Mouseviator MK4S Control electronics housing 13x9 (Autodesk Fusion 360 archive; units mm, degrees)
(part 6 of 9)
sketch "Sketch1" plane through (0, 0, 5) normal (0, 0, 1) x axis (-1, 0, 0)
  line L1 (-98.9644, -53.9879) -> (-98.9644, -59.9879)
  line L2 (-92.9644, -53.9879) -> (-98.9644, -53.9879)
  line L3 (-92.9644, -59.9879) -> (-92.9644, -53.9879)
  line L4 (-98.9644, -59.9879) -> (-92.9644, -59.9879)
  line L5 (-12.9644, 60.0121) -> (-12.9644, 66.0121)
  line L6 (-18.9644, 60.0121) -> (-12.9644, 60.0121)
  line L7 (-18.9644, 66.0121) -> (-18.9644, 60.0121)
  line L8 (-12.9644, 66.0121) -> (-18.9644, 66.0121)
  line L9 (-45.9644, -51.9879) -> (-20.9644, -51.9879)
  line L10 (-40.9644, -54.9879) -> (-45.9644, -51.9879)
  line L11 (-70.9644, -54.9879) -> (-40.9644, -54.9879)
  line L12 (-65.9644, -51.9879) -> (-70.9644, -54.9879)
  line L13 (-90.9644, -51.9879) -> (-65.9644, -51.9879)
  line L14 (-90.9644, -6.9879) -> (-90.9644, -51.9879)
  line L15 (-93.9644, -11.9879) -> (-90.9644, -6.9879)
  line L16 (-93.9644, 18.0121) -> (-93.9644, -11.9879)
  line L17 (-90.9644, 13.0121) -> (-93.9644, 18.0121)
  line L18 (-90.9644, 58.0121) -> (-90.9644, 13.0121)
  line L19 (-65.9644, 58.0121) -> (-90.9644, 58.0121)
  line L20 (-70.9644, 61.0121) -> (-65.9644, 58.0121)
  line L21 (-40.9644, 61.0121) -> (-70.9644, 61.0121)
  line L22 (-45.9644, 58.0121) -> (-40.9644, 61.0121)
  line L23 (-20.9644, 58.0121) -> (-45.9644, 58.0121)
  line L24 (-20.9644, 13.0121) -> (-20.9644, 58.0121)
  line L25 (-17.9644, 18.0121) -> (-20.9644, 13.0121)
  line L26 (-17.9644, -11.9879) -> (-17.9644, 18.0121)
  line L27 (-20.9644, -6.9879) -> (-17.9644, -11.9879)
  line L28 (-20.9644, -51.9879) -> (-20.9644, -6.9879)
  line L29 (-12.9644, -53.9879) -> (-18.9644, -53.9879)
  line L30 (-12.9644, -59.9879) -> (-12.9644, -53.9879)
  line L31 (-18.9644, -59.9879) -> (-12.9644, -59.9879)
  line L32 (-18.9644, -53.9879) -> (-18.9644, -59.9879)
  line L33 (-98.9644, 60.0121) -> (-92.9644, 60.0121)
  line L34 (-98.9644, 66.0121) -> (-98.9644, 60.0121)
  line L35 (-92.9644, 66.0121) -> (-98.9644, 66.0121)
  line L36 (-92.9644, 60.0121) -> (-92.9644, 66.0121)
  line L37 (-10.9644, -6.9879) -> (-10.9644, -61.9879)
  line L38 (-13.9644, -11.9879) -> (-10.9644, -6.9879)
  line L39 (-13.9644, 18.0121) -> (-13.9644, -11.9879)
  line L40 (-10.9644, 13.0121) -> (-13.9644, 18.0121)
  line L41 (-10.9644, 68.0121) -> (-10.9644, 13.0121)
  line L42 (-45.9644, 68.0121) -> (-10.9644, 68.0121)
  line L43 (-40.9644, 65.0121) -> (-45.9644, 68.0121)
  line L44 (-70.9644, 65.0121) -> (-40.9644, 65.0121)
  line L45 (-65.9644, 68.0121) -> (-70.9644, 65.0121)
  line L46 (-100.9644, 68.0121) -> (-65.9644, 68.0121)
  line L47 (-100.9644, 13.0121) -> (-100.9644, 68.0121)
  line L48 (-97.9644, 18.0121) -> (-100.9644, 13.0121)
  line L49 (-97.9644, -11.9879) -> (-97.9644, 18.0121)
  line L50 (-100.9644, -6.9879) -> (-97.9644, -11.9879)
  line L51 (-100.9644, -61.9879) -> (-100.9644, -6.9879)
  line L52 (-65.9644, -61.9879) -> (-100.9644, -61.9879)
  line L53 (-70.9644, -58.9879) -> (-65.9644, -61.9879)
  line L54 (-40.9644, -58.9879) -> (-70.9644, -58.9879)
  line L55 (-45.9644, -61.9879) -> (-40.9644, -58.9879)
  line L56 (-10.9644, -61.9879) -> (-45.9644, -61.9879)
  line L57 (-100.9644, -61.9879) -> (-10.9644, -61.9879)
  line L58 (-99.9644, -60.9879) -> (-100.9644, -61.9879)
  line L59 (-91.9644, -60.9879) -> (-99.9644, -60.9879)
  line L60 (-91.9644, -59.9879) -> (-91.9644, -60.9879)
  line L61 (-19.9644, -59.9879) -> (-91.9644, -59.9879)
  line L62 (-19.9644, -60.9879) -> (-19.9644, -59.9879)
  line L63 (-11.9644, -60.9879) -> (-19.9644, -60.9879)
  line L64 (-10.9644, -61.9879) -> (-11.9644, -60.9879)
  line L65 (-99.9437, -61.0379) -> (-100.8937, -61.9879)
  line L66 (-91.9144, -61.0379) -> (-99.9437, -61.0379)
  line L67 (-91.9144, -60.0379) -> (-91.9144, -61.0379)
  line L68 (-20.0144, -60.0379) -> (-91.9144, -60.0379)
  line L69 (-20.0144, -61.0379) -> (-20.0144, -60.0379)
  line L70 (-11.9851, -61.0379) -> (-20.0144, -61.0379)
  line L71 (-11.0351, -61.9879) -> (-11.9851, -61.0379)
  circle C1 centre (-24.4644, 61.5121) radius 1.7
  circle C2 centre (-93.9644, 54.5121) radius 1.7
  circle C3 centre (-87.4644, -55.4879) radius 1.7
  circle C4 centre (-17.4644, -48.4879) radius 1.7
  circle C5 centre (-24.4644, -55.4879) radius 1.7
  circle C6 centre (-93.9644, -48.4879) radius 1.7
  circle C7 centre (-87.4644, 61.5121) radius 1.7
  circle C8 centre (-17.4644, 54.5121) radius 1.7
  point P46 (-10.9644, -61.9879)
  point P74 (-10.9644, -61.9879)
  point P61 (-100.9644, -61.9879)
  point P76 (-100.9644, -61.9879)
  point P68 (-99.9644, -60.9879)
  point P77 (-99.9644, -60.9879)
  point P69 (-91.9644, -60.9879)
  point P78 (-91.9644, -60.9879)
  point P70 (-91.9644, -59.9879)
  point P79 (-91.9644, -59.9879)
  point P71 (-19.9644, -59.9879)
  point P80 (-19.9644, -59.9879)
  point P72 (-19.9644, -60.9879)
  point P81 (-19.9644, -60.9879)
  point P73 (-11.9644, -60.9879)
  point P82 (-11.9644, -60.9879)
  point P89 (-11.0351, -61.9879)
  point P90 (-100.8937, -61.9879)
  point P75 (-100.9644, -61.9879)
  coincident P46 P74
  coincident P61 P76
  coincident P68 P77
  coincident P69 P78
  coincident P70 P79
  coincident P71 P80
  coincident P72 P81
  coincident P73 P82
  coincident L56 P89
  coincident L52 P90
  dimension "d228_1_1" distance L57 L70 = 0.95 (= "side_wall_thick1")
  dimension "d229_1_1" distance L57 L68 = 1.95 (= "side_wall_thick2")
  dimension "d230_1_1" distance L57 L66 = 0.95 (= "side_wall_thick1")
  dimension "d231_1_1" distance P74 P75 = 90 (= "plate_height")
  dimension "d232_1_1" distance L64 L71 = 0.05 (= "wall_clearance")
  dimension "d233_1_1" distance L58 L65 = 0.05 (= "wall_clearance")
  dimension "d234_1_1" angle L57 L58 = 45 (= "wall_rorner_angle")
  dimension "d235_1_1" distance P74 L69 = 9.05 (= "side_wall_col_length")
  dimension "d244_1_1" distance P75 L67 = 9.05 (= "side_wall_col_length")
extrude "Extrude1" new body sketch "Sketch1" profile of L52 L53 L55 L56 blind 69.9 (= "column_height - ( 2 * wall_clearance )") named "d217_1_1" from offset 0.05 (= "wall_clearance") named "d216_1_1"
sketch "Sketch2" plane through (0, 61.9879, 0) normal (0, 1, 0) x axis (-1, 0, 0)
  line L1 (-11.0351, 74.95) -> (-100.8937, 74.95)
  line L2 (-100.8937, 74.95) -> (-100.8937, 5.05)
  line L3 (-11.0351, 74.95) -> (-11.0351, 5.05)
  line L4 (-11.0351, 5.05) -> (-100.8937, 5.05)
  line L5 (-11.0351, 74.95) -> (-11.0351, 5.05)
  line L6 (-100.8937, 74.95) -> (-11.0351, 74.95)
  line L7 (-100.8937, 5.05) -> (-100.8937, 74.95)
  line L8 (-90.8937, 64.95) -> (-21.0351, 64.95)
  line L9 (-90.8937, 15.05) -> (-90.8937, 64.95)
  line L10 (-21.0351, 15.05) -> (-90.8937, 15.05)
  line L11 (-21.0351, 64.95) -> (-21.0351, 15.05)
  circle C1 centre (-95.9644, 60) radius 1.7
  circle C2 centre (-95.9644, 20) radius 1.7
  circle C3 centre (-15.9644, 20) radius 1.7
  circle C4 centre (-15.9644, 60) radius 1.7
sketch "Sketch3" plane through (0, 61.9879, 0) normal (0, 1, 0) x axis (-1, 0, 0)
  line L1 (-11.0351, 5.05) -> (-100.8937, 5.05)
  line L2 (-11.0351, 74.95) -> (-11.0351, 5.05)
  line L3 (-100.8937, 74.95) -> (-11.0351, 74.95)
  line L4 (-100.8937, 5.05) -> (-100.8937, 74.95)
  line L5 (-55.9644, -6.6527) -> (-55.9644, 156.5527)
  line L6 (83.5909, 40) -> (-105.6612, 40)
  line L7 (-100.8937, 64.95) -> (-100.8937, 74.95)
  line L8 (-94.8937, 74.95) -> (-100.8937, 74.95)
  line L9 (-94.8937, 59.95) -> (-94.8937, 74.95)
  line L10 (-100.8937, 64.95) -> (-94.8937, 59.95)
  line L11 (-100.9437, 64.9735) -> (-106.8437, 60)
  line L12 (-106.8437, 60) -> (-106.8437, 74.9)
  line L13 (-100.8937, 64.9735) -> (-100.9437, 64.9735)
  line L14 (-100.8937, 74.9) -> (-106.8437, 74.9)
  line L15 (-100.8937, 5.1) -> (-106.8437, 5.1)
  line L16 (-106.8437, 20) -> (-106.8437, 5.1)
  line L17 (-100.9437, 15.0265) -> (-106.8437, 20)
  line L18 (-100.8937, 15.0265) -> (-100.9437, 15.0265)
  line L19 (-100.8937, 15.05) -> (-100.8937, 5.05)
  line L20 (-94.8937, 5.05) -> (-100.8937, 5.05)
  line L21 (-94.8937, 20.05) -> (-94.8937, 5.05)
  line L22 (-100.8937, 15.05) -> (-94.8937, 20.05)
  line L23 (-11.0351, 5.1) -> (-5.0851, 5.1)
  line L24 (-5.0851, 20) -> (-5.0851, 5.1)
  line L25 (-10.9851, 15.0265) -> (-5.0851, 20)
  line L26 (-11.0351, 15.0265) -> (-10.9851, 15.0265)
  line L27 (-11.0351, 15.05) -> (-11.0351, 5.05)
  line L28 (-17.0351, 5.05) -> (-11.0351, 5.05)
  line L29 (-17.0351, 20.05) -> (-17.0351, 5.05)
  line L30 (-11.0351, 15.05) -> (-17.0351, 20.05)
  line L31 (-11.0351, 74.9) -> (-5.0851, 74.9)
  line L32 (-5.0851, 60) -> (-5.0851, 74.9)
  line L33 (-11.0351, 64.9735) -> (-10.9851, 64.9735)
  line L34 (-10.9851, 64.9735) -> (-5.0851, 60)
  line L35 (-11.0351, 64.95) -> (-11.0351, 74.95)
  line L36 (-17.0351, 74.95) -> (-11.0351, 74.95)
  line L37 (-17.0351, 59.95) -> (-17.0351, 74.95)
  line L38 (-11.0351, 64.95) -> (-17.0351, 59.95)
  circle C1 centre (-95.9644, 20) radius 1.7
  circle C2 centre (-15.9644, 20) radius 1.7
  circle C3 centre (-15.9644, 60) radius 1.7
  circle C4 centre (-95.9644, 60) radius 1.7
  circle C5 centre (-15.9644, 20) radius 1.45
  circle C6 centre (-15.9644, 60) radius 1.45
  circle C7 centre (-95.9644, 60) radius 1.45
  circle C8 centre (-95.9644, 20) radius 1.45
  point P17 (-100.8937, 64.9735)
  point P18 (-100.8937, 74.9)
  point P10 (-100.8937, 74.95)
  point P24 (-100.8937, 5.05)
  point P11 (-100.8937, 64.95)
  point P25 (-100.8937, 15.05)
  point P12 (-94.8937, 74.95)
  point P26 (-94.8937, 5.05)
  point P13 (-94.8937, 59.95)
  point P27 (-94.8937, 20.05)
  point P14 (-100.9437, 64.9735)
  point P22 (-100.9437, 15.0265)
  point P15 (-106.8437, 60)
  point P21 (-106.8437, 20)
  point P16 (-106.8437, 74.9)
  point P19 (-106.8437, 5.1)
  point P23 (-100.8937, 15.0265)
  point P20 (-100.8937, 5.1)
  point P42 (-11.0351, 74.95)
  point P43 (-11.0351, 64.95)
  point P44 (-17.0351, 74.95)
  point P45 (-17.0351, 59.95)
  point P40 (-10.9851, 64.9735)
  point P39 (-5.0851, 60)
  point P37 (-5.0851, 74.9)
  point P41 (-11.0351, 64.9735)
  point P38 (-11.0351, 74.9)
  point P28 (-5.0851, 5.1)
  point P29 (-11.0351, 5.1)
  point P30 (-5.0851, 20)
  point P31 (-10.9851, 15.0265)
  point P32 (-11.0351, 15.0265)
  point P33 (-11.0351, 5.05)
  point P34 (-11.0351, 15.05)
  point P35 (-17.0351, 5.05)
  point P36 (-17.0351, 20.05)
  vertical L5
  horizontal L6
  midpoint L3 L5
  midpoint L2 L6
  coincident L7 P17
  coincident L4 P17
  perpendicular L7 L14
  coincident L4 P18
  symmetric L6 P10 P24
  symmetric L6 P11 P25
  symmetric L6 P12 P26
  symmetric L6 P13 P27
  symmetric L6 P14 P22
  symmetric L6 P15 P21
  symmetric L6 P16 P19
  symmetric L6 P17 P23
  symmetric L6 P18 P20
  symmetric L5 P10 P42
  symmetric L5 P11 P43
  symmetric L5 P12 P44
  symmetric L5 P13 P45
  symmetric L5 P14 P40
  symmetric L5 P15 P39
  symmetric L5 P16 P37
  symmetric L5 P17 P41
  symmetric L5 P18 P38
  symmetric L5 P19 P28
  symmetric L5 P20 P29
  symmetric L5 P21 P30
  symmetric L5 P22 P31
  symmetric L5 P23 P32
  symmetric L5 P24 P33
  symmetric L5 P25 P34
  symmetric L5 P26 P35
  symmetric L5 P27 P36
  dimension "d332_1_1" distance P12 P13 = 15 (= "join_width2")
  dimension "d333_1_1" distance P10 P12 = 6 (= "join_depth * 2")
  dimension "d334_1_1" distance P10 P11 = 10 (= "join_width1")
  dimension "d336_1_1" distance P15 P16 = 14.9 (= "join_width2 - ( 2 * wall_clearance )")
  dimension "d337_1_1" distance P16 P18 = 5.95 (= "join_depth * 2 - wall_clearance")
  dimension "d338_1_1" distance P14 P17 = 0.05 (= "wall_clearance")
  dimension "d519" = -0.25
  dimension "d520" = -0.25
  dimension "d521" = -0.25
  dimension "d522" = -0.25
position "Position17"
extrude "Extrude3" cut sketch "Sketch3" profile of L1 L2 L3 L4 L7 L8 L9 L10 L19 L20 L21 L22 L27 L28 L29 L30 L35 L36 L37 L38 against normal blind 2 named "d339_1"
position "Position18"
extrude "Extrude4" add sketch "Sketch3" profile of L9 L10 L21 L22 L29 L30 L37 L38 C5 C6 C7 C8 against normal blind 5
sketch "Sketch1" plane through (0, 0, 5) normal (0, 0, 1) x axis (-1, 0, 0)
  circle C1 centre (35, 15) radius 4
  circle C2 centre (35, 15) radius 3.25
  circle C3 centre (35, 15) radius 2.21
  concentric C1 C2
  concentric C2 C3
  dimension "bol_plate_outer_d" diameter C1 = 8
  dimension "bolt_plate_inner_d" diameter C2 = 6.5
  dimension "d527" diameter C3 = 4.42 (= "M3_d * 1.3")
extrude "Extrude1" new body sketch "Sketch1" along normal blind 1.5 named "bolt_d_thick"
extrude "Extrude2" add sketch "Sketch1" profile of C1 C2 along normal blind 3 (= "bolt_d_thick * 2")
fillet "Fillet1" radius 1.5 (= "bolt_d_thick")
sketch "Sketch1" plane through (0, 0, 5) normal (0, 0, 1) x axis (-1, 0, 0)
  line L1 (-98.9644, -53.9879) -> (-98.9644, -59.9879)
  line L2 (-92.9644, -53.9879) -> (-98.9644, -53.9879)
  line L3 (-92.9644, -59.9879) -> (-92.9644, -53.9879)
  line L4 (-98.9644, -59.9879) -> (-92.9644, -59.9879)
  line L5 (-12.9644, 60.0121) -> (-12.9644, 66.0121)
  line L6 (-18.9644, 60.0121) -> (-12.9644, 60.0121)
  line L7 (-18.9644, 66.0121) -> (-18.9644, 60.0121)
  line L8 (-12.9644, 66.0121) -> (-18.9644, 66.0121)
  line L9 (-45.9644, -51.9879) -> (-20.9644, -51.9879)
  line L10 (-40.9644, -54.9879) -> (-45.9644, -51.9879)
  line L11 (-70.9644, -54.9879) -> (-40.9644, -54.9879)
  line L12 (-65.9644, -51.9879) -> (-70.9644, -54.9879)
  line L13 (-90.9644, -51.9879) -> (-65.9644, -51.9879)
  line L14 (-90.9644, -6.9879) -> (-90.9644, -51.9879)
  line L15 (-93.9644, -11.9879) -> (-90.9644, -6.9879)
  line L16 (-93.9644, 18.0121) -> (-93.9644, -11.9879)
  line L17 (-90.9644, 13.0121) -> (-93.9644, 18.0121)
  line L18 (-90.9644, 58.0121) -> (-90.9644, 13.0121)
  line L19 (-65.9644, 58.0121) -> (-90.9644, 58.0121)
  line L20 (-70.9644, 61.0121) -> (-65.9644, 58.0121)
  line L21 (-40.9644, 61.0121) -> (-70.9644, 61.0121)
  line L22 (-45.9644, 58.0121) -> (-40.9644, 61.0121)
  line L23 (-20.9644, 58.0121) -> (-45.9644, 58.0121)
  line L24 (-20.9644, 13.0121) -> (-20.9644, 58.0121)
  line L25 (-17.9644, 18.0121) -> (-20.9644, 13.0121)
  line L26 (-17.9644, -11.9879) -> (-17.9644, 18.0121)
  line L27 (-20.9644, -6.9879) -> (-17.9644, -11.9879)
  line L28 (-20.9644, -51.9879) -> (-20.9644, -6.9879)
  line L29 (-12.9644, -53.9879) -> (-18.9644, -53.9879)
  line L30 (-12.9644, -59.9879) -> (-12.9644, -53.9879)
  line L31 (-18.9644, -59.9879) -> (-12.9644, -59.9879)
  line L32 (-18.9644, -53.9879) -> (-18.9644, -59.9879)
  line L33 (-98.9644, 60.0121) -> (-92.9644, 60.0121)
  line L34 (-98.9644, 66.0121) -> (-98.9644, 60.0121)
  line L35 (-92.9644, 66.0121) -> (-98.9644, 66.0121)
  line L36 (-92.9644, 60.0121) -> (-92.9644, 66.0121)
  line L37 (-10.9644, -6.9879) -> (-10.9644, -61.9879)
  line L38 (-13.9644, -11.9879) -> (-10.9644, -6.9879)
  line L39 (-13.9644, 18.0121) -> (-13.9644, -11.9879)
  line L40 (-10.9644, 13.0121) -> (-13.9644, 18.0121)
  line L41 (-10.9644, 68.0121) -> (-10.9644, 13.0121)
  line L42 (-45.9644, 68.0121) -> (-10.9644, 68.0121)
  line L43 (-40.9644, 65.0121) -> (-45.9644, 68.0121)
  line L44 (-70.9644, 65.0121) -> (-40.9644, 65.0121)
  line L45 (-65.9644, 68.0121) -> (-70.9644, 65.0121)
  line L46 (-100.9644, 68.0121) -> (-65.9644, 68.0121)
  line L47 (-100.9644, 13.0121) -> (-100.9644, 68.0121)
  line L48 (-97.9644, 18.0121) -> (-100.9644, 13.0121)
  line L49 (-97.9644, -11.9879) -> (-97.9644, 18.0121)
  line L50 (-100.9644, -6.9879) -> (-97.9644, -11.9879)
  line L51 (-100.9644, -61.9879) -> (-100.9644, -6.9879)
  line L52 (-65.9644, -61.9879) -> (-100.9644, -61.9879)
  line L53 (-70.9644, -58.9879) -> (-65.9644, -61.9879)
  line L54 (-40.9644, -58.9879) -> (-70.9644, -58.9879)
  line L55 (-45.9644, -61.9879) -> (-40.9644, -58.9879)
  line L56 (-10.9644, -61.9879) -> (-45.9644, -61.9879)
  line L57 (-100.9644, -61.9879) -> (-10.9644, -61.9879)
  line L58 (-99.9644, -60.9879) -> (-100.9644, -61.9879)
  line L59 (-91.9644, -60.9879) -> (-99.9644, -60.9879)
  line L60 (-91.9644, -59.9879) -> (-91.9644, -60.9879)
  line L61 (-19.9644, -59.9879) -> (-91.9644, -59.9879)
  line L62 (-19.9644, -60.9879) -> (-19.9644, -59.9879)
  line L63 (-11.9644, -60.9879) -> (-19.9644, -60.9879)
  line L64 (-10.9644, -61.9879) -> (-11.9644, -60.9879)
  line L65 (-99.9437, -61.0379) -> (-100.8937, -61.9879)
  line L66 (-91.9144, -61.0379) -> (-99.9437, -61.0379)
  line L67 (-91.9144, -60.0379) -> (-91.9144, -61.0379)
  line L68 (-20.0144, -60.0379) -> (-91.9144, -60.0379)
  line L69 (-20.0144, -61.0379) -> (-20.0144, -60.0379)
  line L70 (-11.9851, -61.0379) -> (-20.0144, -61.0379)
  line L71 (-11.0351, -61.9879) -> (-11.9851, -61.0379)
  circle C1 centre (-24.4644, 61.5121) radius 1.7
  circle C2 centre (-93.9644, 54.5121) radius 1.7
  circle C3 centre (-87.4644, -55.4879) radius 1.7
  circle C4 centre (-17.4644, -48.4879) radius 1.7
  circle C5 centre (-24.4644, -55.4879) radius 1.7
  circle C6 centre (-93.9644, -48.4879) radius 1.7
  circle C7 centre (-87.4644, 61.5121) radius 1.7
  circle C8 centre (-17.4644, 54.5121) radius 1.7
  point P46 (-10.9644, -61.9879)
  point P74 (-10.9644, -61.9879)
  point P61 (-100.9644, -61.9879)
  point P76 (-100.9644, -61.9879)
  point P68 (-99.9644, -60.9879)
  point P77 (-99.9644, -60.9879)
  point P69 (-91.9644, -60.9879)
  point P78 (-91.9644, -60.9879)
  point P70 (-91.9644, -59.9879)
  point P79 (-91.9644, -59.9879)
  point P71 (-19.9644, -59.9879)
  point P80 (-19.9644, -59.9879)
  point P72 (-19.9644, -60.9879)
  point P81 (-19.9644, -60.9879)
  point P73 (-11.9644, -60.9879)
  point P82 (-11.9644, -60.9879)
  point P89 (-11.0351, -61.9879)
  point P90 (-100.8937, -61.9879)
  point P75 (-100.9644, -61.9879)
  coincident P46 P74
  coincident P61 P76
  coincident P68 P77
  coincident P69 P78
  coincident P70 P79
  coincident P71 P80
  coincident P72 P81
  coincident P73 P82
  coincident L56 P89
  coincident L52 P90
  dimension "d228_3_1" distance L57 L70 = 0.95 (= "side_wall_thick1")
  dimension "d229_3_1" distance L57 L68 = 1.95 (= "side_wall_thick2")
  dimension "d230_3_1" distance L57 L66 = 0.95 (= "side_wall_thick1")
  dimension "d231_3_1" distance P74 P75 = 90 (= "plate_height")
  dimension "d232_3_1" distance L64 L71 = 0.05 (= "wall_clearance")
  dimension "d233_3_1" distance L58 L65 = 0.05 (= "wall_clearance")
  dimension "d234_3_1" angle L57 L58 = 45 (= "wall_rorner_angle")
  dimension "d235_3_1" distance P74 L69 = 9.05 (= "side_wall_col_length")
  dimension "d244_3_1" distance P75 L67 = 9.05 (= "side_wall_col_length")
extrude "Extrude1" new body sketch "Sketch1" profile of L52 L53 L55 L56 blind 69.9 (= "column_height - ( 2 * wall_clearance )") named "d217_3_1" from offset 0.05 (= "wall_clearance") named "d216_3_1"
sketch "Sketch2" plane through (0, 61.9879, 0) normal (0, 1, 0) x axis (-1, 0, 0)
  line L1 (-11.0351, 74.95) -> (-100.8937, 74.95)
  line L2 (-100.8937, 74.95) -> (-100.8937, 5.05)
  line L3 (-11.0351, 74.95) -> (-11.0351, 5.05)
  line L4 (-11.0351, 5.05) -> (-100.8937, 5.05)
  line L5 (-11.0351, 74.95) -> (-11.0351, 5.05)
  line L6 (-100.8937, 74.95) -> (-11.0351, 74.95)
  line L7 (-100.8937, 5.05) -> (-100.8937, 74.95)
  line L8 (-90.8937, 64.95) -> (-21.0351, 64.95)
  line L9 (-90.8937, 15.05) -> (-90.8937, 64.95)
  line L10 (-21.0351, 15.05) -> (-90.8937, 15.05)
  line L11 (-21.0351, 64.95) -> (-21.0351, 15.05)
  circle C1 centre (-95.9644, 60) radius 1.7
  circle C2 centre (-95.9644, 20) radius 1.7
  circle C3 centre (-15.9644, 20) radius 1.7
  circle C4 centre (-15.9644, 60) radius 1.7
hole "Hole1" HoleDepth 4 named "d220_3_1" HoleDiameter 3.4 named "d221_3_1" TipAngle 118 named "d222_3_1"
sketch "Sketch3" plane through (0, 61.9879, 0) normal (0, 1, 0) x axis (-1, 0, 0)
  line L1 (-11.0351, 5.05) -> (-100.8937, 5.05)
  line L2 (-11.0351, 74.95) -> (-11.0351, 5.05)
  line L3 (-100.8937, 74.95) -> (-11.0351, 74.95)
  line L4 (-100.8937, 5.05) -> (-100.8937, 74.95)
  line L5 (-55.9644, -6.6527) -> (-55.9644, 156.5527)
  line L6 (83.5909, 40) -> (-105.6612, 40)
  line L7 (-100.8937, 64.95) -> (-100.8937, 74.95)
  line L8 (-94.8937, 74.95) -> (-100.8937, 74.95)
  line L9 (-94.8937, 59.95) -> (-94.8937, 74.95)
  line L10 (-100.8937, 64.95) -> (-94.8937, 59.95)
  line L11 (-100.9437, 64.9735) -> (-106.8437, 60)
  line L12 (-106.8437, 60) -> (-106.8437, 74.9)
  line L13 (-100.8937, 64.9735) -> (-100.9437, 64.9735)
  line L14 (-100.8937, 74.9) -> (-106.8437, 74.9)
  line L15 (-100.8937, 5.1) -> (-106.8437, 5.1)
  line L16 (-106.8437, 20) -> (-106.8437, 5.1)
  line L17 (-100.9437, 15.0265) -> (-106.8437, 20)
  line L18 (-100.8937, 15.0265) -> (-100.9437, 15.0265)
  line L19 (-100.8937, 15.05) -> (-100.8937, 5.05)
  line L20 (-94.8937, 5.05) -> (-100.8937, 5.05)
  line L21 (-94.8937, 20.05) -> (-94.8937, 5.05)
  line L22 (-100.8937, 15.05) -> (-94.8937, 20.05)
  line L23 (-11.0351, 5.1) -> (-5.0851, 5.1)
  line L24 (-5.0851, 20) -> (-5.0851, 5.1)
  line L25 (-10.9851, 15.0265) -> (-5.0851, 20)
  line L26 (-11.0351, 15.0265) -> (-10.9851, 15.0265)
  line L27 (-11.0351, 15.05) -> (-11.0351, 5.05)
  line L28 (-17.0351, 5.05) -> (-11.0351, 5.05)
  line L29 (-17.0351, 20.05) -> (-17.0351, 5.05)
  line L30 (-11.0351, 15.05) -> (-17.0351, 20.05)
  line L31 (-11.0351, 74.9) -> (-5.0851, 74.9)
  line L32 (-5.0851, 60) -> (-5.0851, 74.9)
  line L33 (-11.0351, 64.9735) -> (-10.9851, 64.9735)
  line L34 (-10.9851, 64.9735) -> (-5.0851, 60)
  line L35 (-11.0351, 64.95) -> (-11.0351, 74.95)
  line L36 (-17.0351, 74.95) -> (-11.0351, 74.95)
  line L37 (-17.0351, 59.95) -> (-17.0351, 74.95)
  line L38 (-11.0351, 64.95) -> (-17.0351, 59.95)
  point P17 (-100.8937, 64.9735)
  point P18 (-100.8937, 74.9)
  point P10 (-100.8937, 74.95)
  point P24 (-100.8937, 5.05)
  point P11 (-100.8937, 64.95)
  point P25 (-100.8937, 15.05)
  point P12 (-94.8937, 74.95)
  point P26 (-94.8937, 5.05)
  point P13 (-94.8937, 59.95)
  point P27 (-94.8937, 20.05)
  point P14 (-100.9437, 64.9735)
  point P22 (-100.9437, 15.0265)
  point P15 (-106.8437, 60)
  point P21 (-106.8437, 20)
  point P16 (-106.8437, 74.9)
  point P19 (-106.8437, 5.1)
  point P23 (-100.8937, 15.0265)
  point P20 (-100.8937, 5.1)
  point P42 (-11.0351, 74.95)
  point P43 (-11.0351, 64.95)
  point P44 (-17.0351, 74.95)
  point P45 (-17.0351, 59.95)
  point P40 (-10.9851, 64.9735)
  point P39 (-5.0851, 60)
  point P37 (-5.0851, 74.9)
  point P41 (-11.0351, 64.9735)
  point P38 (-11.0351, 74.9)
  point P28 (-5.0851, 5.1)
  point P29 (-11.0351, 5.1)
  point P30 (-5.0851, 20)
  point P31 (-10.9851, 15.0265)
  point P32 (-11.0351, 15.0265)
  point P33 (-11.0351, 5.05)
  point P34 (-11.0351, 15.05)
  point P35 (-17.0351, 5.05)
  point P36 (-17.0351, 20.05)
  vertical L5
  horizontal L6
  midpoint L3 L5
  midpoint L2 L6
  coincident L7 P17
  coincident L4 P17
  perpendicular L7 L14
  coincident L4 P18
  symmetric L6 P10 P24
  symmetric L6 P11 P25
  symmetric L6 P12 P26
  symmetric L6 P13 P27
  symmetric L6 P14 P22
  symmetric L6 P15 P21
  symmetric L6 P16 P19
  symmetric L6 P17 P23
  symmetric L6 P18 P20
  symmetric L5 P10 P42
  symmetric L5 P11 P43
  symmetric L5 P12 P44
  symmetric L5 P13 P45
  symmetric L5 P14 P40
  symmetric L5 P15 P39
  symmetric L5 P16 P37
  symmetric L5 P17 P41
  symmetric L5 P18 P38
  symmetric L5 P19 P28
  symmetric L5 P20 P29
  symmetric L5 P21 P30
  symmetric L5 P22 P31
  symmetric L5 P23 P32
  symmetric L5 P24 P33
  symmetric L5 P25 P34
  symmetric L5 P26 P35
  symmetric L5 P27 P36
  dimension "d332_3_1" distance P12 P13 = 15 (= "join_width2")
  dimension "d333_3_1" distance P10 P12 = 6 (= "join_depth * 2")
  dimension "d334_3_1" distance P10 P11 = 10 (= "join_width1")
  dimension "d336_3_1" distance P15 P16 = 14.9 (= "join_width2 - ( 2 * wall_clearance )")
  dimension "d337_3_1" distance P16 P18 = 5.95 (= "join_depth * 2 - wall_clearance")
  dimension "d338_3_1" distance P14 P17 = 0.05 (= "wall_clearance")
position "Position19"
extrude "Extrude3" add sketch "Sketch3" profile of L1 L3 L4 L7 L8 L9 L10 L12 L11 L13 L14 L15 L16 L17 L18 L19 L20 L21 L22 against normal blind 0.95 named "d343_1" (magnitude of "-side_wall_thick1")
sketch "Sketch4" plane through (0, 61.9879, 0) normal (0, 1, 0) x axis (1, 0, 0)
  line L1 (11.0351, -5.05) -> (100.8937, -5.05)
  line L2 (11.0351, -74.95) -> (11.0351, -5.05)
  line L3 (100.8937, -74.95) -> (11.0351, -74.95)
  line L4 (100.8937, -5.05) -> (100.8937, -74.95)
  line L5 (36.6374, -5.05) -> (36.6374, -12.415)
  line L6 (26.6374, -5.05) -> (26.6374, -12.415)
  circle C1 centre (15.9644, -20) radius 1.7
  circle C2 centre (95.9644, -60) radius 1.7
  circle C3 centre (95.9644, -20) radius 1.7
  circle C4 centre (15.9644, -60) radius 1.7
  arc A1 centre (31.6374, -12.415) radius 5 clockwise from (36.6374, -12.415) to (26.6374, -12.415)
  point P12 (36.6374, -5.05)
  point P14 (26.6374, -5.05)
  coincident L1 P12
  tangent L5 A1
  coincident L1 P14
  tangent L6 A1
  perpendicular L1 L6
  dimension "cable_hole_d_1" diameter A1 = 10
sketch "wall_base" plane through (0, 0, 5) normal (0, 0, 1) x axis (-1, 0, 0)
  line L1 (-98.9644, -53.9879) -> (-98.9644, -59.9879)
  line L2 (-92.9644, -53.9879) -> (-98.9644, -53.9879)
  line L3 (-92.9644, -59.9879) -> (-92.9644, -53.9879)
  line L4 (-98.9644, -59.9879) -> (-92.9644, -59.9879)
  line L5 (-12.9644, 60.0121) -> (-12.9644, 66.0121)
  line L6 (-18.9644, 60.0121) -> (-12.9644, 60.0121)
  line L7 (-18.9644, 66.0121) -> (-18.9644, 60.0121)
  line L8 (-12.9644, 66.0121) -> (-18.9644, 66.0121)
  line L9 (-45.9644, -51.9879) -> (-20.9644, -51.9879)
  line L10 (-40.9644, -54.9879) -> (-45.9644, -51.9879)
  line L11 (-70.9644, -54.9879) -> (-40.9644, -54.9879)
  line L12 (-65.9644, -51.9879) -> (-70.9644, -54.9879)
  line L13 (-90.9644, -51.9879) -> (-65.9644, -51.9879)
  line L14 (-90.9644, -6.9879) -> (-90.9644, -51.9879)
  line L15 (-93.9644, -11.9879) -> (-90.9644, -6.9879)
  line L16 (-93.9644, 18.0121) -> (-93.9644, -11.9879)
  line L17 (-90.9644, 13.0121) -> (-93.9644, 18.0121)
  line L18 (-90.9644, 58.0121) -> (-90.9644, 13.0121)
  line L19 (-65.9644, 58.0121) -> (-90.9644, 58.0121)
  line L20 (-70.9644, 61.0121) -> (-65.9644, 58.0121)
  line L21 (-40.9644, 61.0121) -> (-70.9644, 61.0121)
  line L22 (-45.9644, 58.0121) -> (-40.9644, 61.0121)
  line L23 (-20.9644, 58.0121) -> (-45.9644, 58.0121)
  line L24 (-20.9644, 13.0121) -> (-20.9644, 58.0121)
  line L25 (-17.9644, 18.0121) -> (-20.9644, 13.0121)
  line L26 (-17.9644, -11.9879) -> (-17.9644, 18.0121)
  line L27 (-20.9644, -6.9879) -> (-17.9644, -11.9879)
  line L28 (-20.9644, -51.9879) -> (-20.9644, -6.9879)
  line L29 (-12.9644, -53.9879) -> (-18.9644, -53.9879)
  line L30 (-12.9644, -59.9879) -> (-12.9644, -53.9879)
  line L31 (-18.9644, -59.9879) -> (-12.9644, -59.9879)
  line L32 (-18.9644, -53.9879) -> (-18.9644, -59.9879)
  line L33 (-98.9644, 60.0121) -> (-92.9644, 60.0121)
  line L34 (-98.9644, 66.0121) -> (-98.9644, 60.0121)
  line L35 (-92.9644, 66.0121) -> (-98.9644, 66.0121)
  line L36 (-92.9644, 60.0121) -> (-92.9644, 66.0121)
  line L37 (-10.9644, -6.9879) -> (-10.9644, -61.9879)
  line L38 (-13.9644, -11.9879) -> (-10.9644, -6.9879)
  line L39 (-13.9644, 18.0121) -> (-13.9644, -11.9879)
  line L40 (-10.9644, 13.0121) -> (-13.9644, 18.0121)
  line L41 (-10.9644, 68.0121) -> (-10.9644, 13.0121)
  line L42 (-45.9644, 68.0121) -> (-10.9644, 68.0121)
  line L43 (-40.9644, 65.0121) -> (-45.9644, 68.0121)
  line L44 (-70.9644, 65.0121) -> (-40.9644, 65.0121)
  line L45 (-65.9644, 68.0121) -> (-70.9644, 65.0121)
  line L46 (-100.9644, 68.0121) -> (-65.9644, 68.0121)
  line L47 (-100.9644, 13.0121) -> (-100.9644, 68.0121)
  line L48 (-97.9644, 18.0121) -> (-100.9644, 13.0121)
  line L49 (-97.9644, -11.9879) -> (-97.9644, 18.0121)
  line L50 (-100.9644, -6.9879) -> (-97.9644, -11.9879)
  line L51 (-100.9644, -61.9879) -> (-100.9644, -6.9879)
  line L52 (-65.9644, -61.9879) -> (-100.9644, -61.9879)
  line L53 (-70.9644, -58.9879) -> (-65.9644, -61.9879)
  line L54 (-40.9644, -58.9879) -> (-70.9644, -58.9879)
  line L55 (-45.9644, -61.9879) -> (-40.9644, -58.9879)
  line L56 (-10.9644, -61.9879) -> (-45.9644, -61.9879)
  line L57 (-100.9644, -61.9879) -> (-100.9644, 68.0121)
  line L58 (-100.9644, -61.9172) -> (-100.0144, -60.9672)
  line L59 (-100.0144, -52.9379) -> (-100.0144, -60.9672)
  line L60 (-99.0144, -52.9379) -> (-100.0144, -52.9379)
  line L61 (-99.0144, 58.9451) -> (-99.0144, -52.9379)
  line L62 (-100.0144, 58.9621) -> (-99.0144, 58.9451)
  line L63 (-100.0144, 66.9914) -> (-100.0144, 58.9621)
  line L64 (-100.9644, 67.9414) -> (-100.0144, 66.9914)
  line L65 (-99.9644, -52.9879) -> (-99.9644, -60.9879)
  line L66 (-98.9644, -52.9879) -> (-99.9644, -52.9879)
  line L67 (-98.9644, 58.9942) -> (-98.9644, -52.9879)
  line L68 (-99.9644, 59.0113) -> (-98.9644, 58.9942)
  line L69 (-99.9644, 67.0121) -> (-99.9644, 59.0113)
  line L70 (-100.9644, -61.9879) -> (-99.9644, -60.9879)
  line L71 (-100.9644, 68.0121) -> (-99.9644, 67.0121)
  circle C1 centre (-24.4644, 61.5121) radius 1.7
  circle C2 centre (-93.9644, 54.5121) radius 1.7
  circle C3 centre (-87.4644, -55.4879) radius 1.7
  circle C4 centre (-17.4644, -48.4879) radius 1.7
  circle C5 centre (-24.4644, -55.4879) radius 1.7
  circle C6 centre (-93.9644, -48.4879) radius 1.7
  circle C7 centre (-87.4644, 61.5121) radius 1.7
  circle C8 centre (-17.4644, 54.5121) radius 1.7
  point P69 (-100.9644, 68.0121)
  point P74 (-100.9644, 68.0121)
  point P68 (-100.9644, -61.9879)
  point P75 (-100.9644, -61.9879)
  point P82 (-100.9644, 67.9414)
  point P83 (-100.9644, -61.9172)
  point P90 (-100.9644, -61.9879)
  point P91 (-100.9644, 68.0121)
  point P77 (-100.0144, -52.9379)
  point P80 (-100.0144, 58.9621)
  coincident P69 P74
  coincident P68 P75
  coincident L47 P82
  coincident L51 P83
  coincident P68 P90
  parallel L58 L70
  coincident P69 P91
  dimension "d147_2_1" distance L57 L63 = 0.95 (= "side_wall_thick1")
  dimension "d148_2_1" distance L57 L61 = 1.95 (= "side_wall_thick2")
  dimension "d151_2_1" distance L57 L59 = 0.95 (= "side_wall_thick1")
  dimension "d157_2_1" distance L64 L71 = 0.05 (= "wall_clearance")
  dimension "d158_2_1" distance L58 L70 = 0.05 (= "wall_clearance")
  dimension "wall_rorner_angle_2_1" angle L46 L71 = 45
  dimension "d165_2_1" angle L52 L70 = 45 (= "wall_rorner_angle_2_1")
  dimension "d170_2_1" distance P75 P77 = 9.05
  dimension "d175_2_1" distance P74 P80 = 9.05 (= "side_wall_col_length")
extrude "Extrude1" new body sketch "wall_base" profile of L47 L48 L50 L51 L57 L58 L59 L62 L61 L60 L63 L64 blind 69.9 (= "column_height - ( 2 * wall_clearance )") named "d128_2_1" from offset 0.05 (= "wall_clearance") named "d127_2_1" bodies "side cover"
sketch "Sketch3" plane through (100.9644, 0, 0) normal (1, 0, 0) x axis (0, 1, 0)
  line L1 (61.9172, 5.05) -> (-67.9414, 5.05)
  line L2 (61.9172, 74.95) -> (61.9172, 5.05)
  line L3 (-67.9414, 74.95) -> (61.9172, 74.95)
  line L4 (-67.9414, 5.05) -> (-67.9414, 74.95)
  line L5 (61.9172, 74.95) -> (-67.9414, 74.95)
  line L6 (61.9172, 74.95) -> (61.9172, 5.05)
  line L7 (61.9172, 5.05) -> (-67.9414, 5.05)
  line L8 (-67.9414, 74.95) -> (-67.9414, 5.05)
  line L9 (-57.9414, 64.95) -> (51.9172, 64.95)
  line L10 (-57.9414, 15.05) -> (-57.9414, 64.95)
  line L11 (51.9172, 15.05) -> (-57.9414, 15.05)
  line L12 (51.9172, 64.95) -> (51.9172, 15.05)
  circle C1 centre (-62.995, 60) radius 1.7
  circle C2 centre (-62.995, 20) radius 1.7
  circle C3 centre (56.9879, 60) radius 1.7
  circle C4 centre (56.9879, 20) radius 1.7
hole "Hole1" HoleDepth 4 named "d134_1_1" HoleDiameter 3.4 named "d135_1_1" TipAngle 118 named "d136_1_1"
sketch "Side locks" plane through (100.9644, 0, 0) normal (1, 0, 0) x axis (0, 1, 0)
  line L1 (61.9172, 74.95) -> (61.9172, 5.05)
  line L2 (-67.9414, 74.95) -> (61.9172, 74.95)
  line L3 (-67.9414, 5.05) -> (-67.9414, 74.95)
  line L4 (61.9172, 5.05) -> (-67.9414, 5.05)
  line L5 (-3.0121, 22.271) -> (-3.0121, 127.629)
  line L6 (25.9775, 40) -> (-161.8603, 40)
  line L7 (-67.9414, 64.95) -> (-67.9414, 74.95)
  line L8 (-61.9414, 74.95) -> (-67.9414, 74.95)
  line L9 (-61.9414, 59.95) -> (-61.9414, 74.95)
  line L10 (-67.9414, 64.95) -> (-61.9414, 59.95)
  line L11 (-67.9471, 64.9636) -> (-73.8914, 60.0101)
  line L12 (-73.8914, 60.0101) -> (-73.8914, 74.9101)
  line L13 (-67.9414, 64.9636) -> (-67.9471, 64.9636)
  line L14 (-67.9414, 74.9101) -> (-73.8914, 74.9101)
  line L15 (-67.9414, 5.0899) -> (-73.8914, 5.0899)
  line L16 (-73.8914, 19.9899) -> (-73.8914, 5.0899)
  line L17 (-67.9471, 15.0364) -> (-73.8914, 19.9899)
  line L18 (-67.9414, 15.0364) -> (-67.9471, 15.0364)
  line L19 (-67.9414, 15.05) -> (-67.9414, 5.05)
  line L20 (-61.9414, 5.05) -> (-67.9414, 5.05)
  line L21 (-61.9414, 20.05) -> (-61.9414, 5.05)
  line L22 (-67.9414, 15.05) -> (-61.9414, 20.05)
  line L23 (61.9172, 64.95) -> (61.9172, 74.95)
  line L24 (55.9172, 74.95) -> (61.9172, 74.95)
  line L25 (55.9172, 59.95) -> (55.9172, 74.95)
  line L26 (61.9172, 64.95) -> (55.9172, 59.95)
  line L27 (61.9172, 74.9101) -> (67.8672, 74.9101)
  line L28 (67.8672, 60.0101) -> (67.8672, 74.9101)
  line L29 (61.9172, 64.9636) -> (61.9229, 64.9636)
  line L30 (61.9229, 64.9636) -> (67.8672, 60.0101)
  line L31 (61.9172, 5.0899) -> (67.8672, 5.0899)
  line L32 (67.8672, 19.9899) -> (67.8672, 5.0899)
  line L33 (61.9172, 15.0364) -> (61.9229, 15.0364)
  line L34 (61.9229, 15.0364) -> (67.8672, 19.9899)
  line L35 (61.9172, 15.05) -> (61.9172, 5.05)
  line L36 (55.9172, 5.05) -> (61.9172, 5.05)
  line L37 (55.9172, 20.05) -> (55.9172, 5.05)
  line L38 (61.9172, 15.05) -> (55.9172, 20.05)
  point P17 (-67.9414, 64.9636)
  point P18 (-67.9414, 74.9101)
  point P10 (-67.9414, 74.95)
  point P24 (-67.9414, 5.05)
  point P11 (-67.9414, 64.95)
  point P25 (-67.9414, 15.05)
  point P12 (-61.9414, 74.95)
  point P26 (-61.9414, 5.05)
  point P13 (-61.9414, 59.95)
  point P27 (-61.9414, 20.05)
  point P14 (-67.9471, 64.9636)
  point P22 (-67.9471, 15.0364)
  point P15 (-73.8914, 60.0101)
  point P21 (-73.8914, 19.9899)
  point P16 (-73.8914, 74.9101)
  point P19 (-73.8914, 5.0899)
  point P23 (-67.9414, 15.0364)
  point P20 (-67.9414, 5.0899)
  point P28 (61.9172, 74.95)
  point P29 (61.9172, 64.95)
  point P30 (55.9172, 74.95)
  point P31 (55.9172, 59.95)
  point P35 (61.9229, 64.9636)
  point P34 (67.8672, 60.0101)
  point P32 (67.8672, 74.9101)
  point P36 (61.9172, 64.9636)
  point P33 (61.9172, 74.9101)
  point P37 (67.8672, 5.0899)
  point P38 (61.9172, 5.0899)
  point P39 (67.8672, 19.9899)
  point P40 (61.9229, 15.0364)
  point P41 (61.9172, 15.0364)
  point P42 (61.9172, 5.05)
  point P43 (61.9172, 15.05)
  point P44 (55.9172, 5.05)
  point P45 (55.9172, 20.05)
  vertical L5
  perpendicular L1 L6
  coincident L7 P17
  horizontal L14
  coincident L3 P18
  symmetric L6 P10 P24
  symmetric L6 P11 P25
  symmetric L6 P12 P26
  symmetric L6 P13 P27
  symmetric L6 P14 P22
  symmetric L6 P15 P21
  symmetric L6 P16 P19
  symmetric L6 P17 P23
  symmetric L6 P18 P20
  midpoint L2 L5
  midpoint L3 L6
  symmetric L5 P10 P28
  symmetric L5 P11 P29
  symmetric L5 P12 P30
  symmetric L5 P13 P31
  symmetric L5 P14 P35
  symmetric L5 P15 P34
  symmetric L5 P16 P32
  symmetric L5 P17 P36
  symmetric L5 P18 P33
  symmetric L5 P19 P37
  symmetric L5 P20 P38
  symmetric L5 P21 P39
  symmetric L5 P22 P40
  symmetric L5 P23 P41
  symmetric L5 P24 P42
  symmetric L5 P25 P43
  symmetric L5 P26 P44
  symmetric L5 P27 P45
  dimension "d315_2_1" distance P12 P13 = 15 (= "join_width2")
  dimension "d316_2_1" distance P10 P11 = 10 (= "join_width1")
  dimension "d317_2_1" distance P10 P12 = 6 (= "join_depth * 2")
  dimension "d320_2_1" distance P16 P18 = 5.95 (= "join_depth * 2 - wall_clearance")
  dimension "d321_2_1" distance P15 P16 = 14.9 (= "join_width2 - 2 * wall_clearance")
position "Position24"
extrude "Extrude3" cut sketch "Side locks" profile of L2 L3 L4 L7 L8 L9 L10 L19 L20 L21 L22 against normal blind 5 named "d324_1"
sketch "wall_base" plane through (0, 0, 5) normal (0, 0, 1) x axis (-1, 0, 0)
  line L1 (-98.9644, -53.9879) -> (-98.9644, -59.9879)
  line L2 (-92.9644, -53.9879) -> (-98.9644, -53.9879)
  line L3 (-92.9644, -59.9879) -> (-92.9644, -53.9879)
  line L4 (-98.9644, -59.9879) -> (-92.9644, -59.9879)
  line L5 (-12.9644, 60.0121) -> (-12.9644, 66.0121)
  line L6 (-18.9644, 60.0121) -> (-12.9644, 60.0121)
  line L7 (-18.9644, 66.0121) -> (-18.9644, 60.0121)
  line L8 (-12.9644, 66.0121) -> (-18.9644, 66.0121)
  line L9 (-45.9644, -51.9879) -> (-20.9644, -51.9879)
  line L10 (-40.9644, -54.9879) -> (-45.9644, -51.9879)
  line L11 (-70.9644, -54.9879) -> (-40.9644, -54.9879)
  line L12 (-65.9644, -51.9879) -> (-70.9644, -54.9879)
  line L13 (-90.9644, -51.9879) -> (-65.9644, -51.9879)
  line L14 (-90.9644, -6.9879) -> (-90.9644, -51.9879)
  line L15 (-93.9644, -11.9879) -> (-90.9644, -6.9879)
  line L16 (-93.9644, 18.0121) -> (-93.9644, -11.9879)
  line L17 (-90.9644, 13.0121) -> (-93.9644, 18.0121)
  line L18 (-90.9644, 58.0121) -> (-90.9644, 13.0121)
  line L19 (-65.9644, 58.0121) -> (-90.9644, 58.0121)
  line L20 (-70.9644, 61.0121) -> (-65.9644, 58.0121)
  line L21 (-40.9644, 61.0121) -> (-70.9644, 61.0121)
  line L22 (-45.9644, 58.0121) -> (-40.9644, 61.0121)
  line L23 (-20.9644, 58.0121) -> (-45.9644, 58.0121)
  line L24 (-20.9644, 13.0121) -> (-20.9644, 58.0121)
  line L25 (-17.9644, 18.0121) -> (-20.9644, 13.0121)
  line L26 (-17.9644, -11.9879) -> (-17.9644, 18.0121)
  line L27 (-20.9644, -6.9879) -> (-17.9644, -11.9879)
  line L28 (-20.9644, -51.9879) -> (-20.9644, -6.9879)
  line L29 (-12.9644, -53.9879) -> (-18.9644, -53.9879)
  line L30 (-12.9644, -59.9879) -> (-12.9644, -53.9879)
  line L31 (-18.9644, -59.9879) -> (-12.9644, -59.9879)
  line L32 (-18.9644, -53.9879) -> (-18.9644, -59.9879)
  line L33 (-98.9644, 60.0121) -> (-92.9644, 60.0121)
  line L34 (-98.9644, 66.0121) -> (-98.9644, 60.0121)
  line L35 (-92.9644, 66.0121) -> (-98.9644, 66.0121)
  line L36 (-92.9644, 60.0121) -> (-92.9644, 66.0121)
  line L37 (-10.9644, -6.9879) -> (-10.9644, -61.9879)
  line L38 (-13.9644, -11.9879) -> (-10.9644, -6.9879)
  line L39 (-13.9644, 18.0121) -> (-13.9644, -11.9879)
  line L40 (-10.9644, 13.0121) -> (-13.9644, 18.0121)
  line L41 (-10.9644, 68.0121) -> (-10.9644, 13.0121)
  line L42 (-45.9644, 68.0121) -> (-10.9644, 68.0121)
  line L43 (-40.9644, 65.0121) -> (-45.9644, 68.0121)
  line L44 (-70.9644, 65.0121) -> (-40.9644, 65.0121)
  line L45 (-65.9644, 68.0121) -> (-70.9644, 65.0121)
  line L46 (-100.9644, 68.0121) -> (-65.9644, 68.0121)
  line L47 (-100.9644, 13.0121) -> (-100.9644, 68.0121)
  line L48 (-97.9644, 18.0121) -> (-100.9644, 13.0121)
  line L49 (-97.9644, -11.9879) -> (-97.9644, 18.0121)
  line L50 (-100.9644, -6.9879) -> (-97.9644, -11.9879)
  line L51 (-100.9644, -61.9879) -> (-100.9644, -6.9879)
  line L52 (-65.9644, -61.9879) -> (-100.9644, -61.9879)
  line L53 (-70.9644, -58.9879) -> (-65.9644, -61.9879)
  line L54 (-40.9644, -58.9879) -> (-70.9644, -58.9879)
  line L55 (-45.9644, -61.9879) -> (-40.9644, -58.9879)
  line L56 (-10.9644, -61.9879) -> (-45.9644, -61.9879)
  line L57 (-100.9644, -61.9879) -> (-100.9644, 68.0121)
  line L58 (-100.9644, -61.9172) -> (-100.0144, -60.9672)
  line L59 (-100.0144, -52.9379) -> (-100.0144, -60.9672)
  line L60 (-99.0144, -52.9379) -> (-100.0144, -52.9379)
  line L61 (-99.0144, 58.9451) -> (-99.0144, -52.9379)
  line L62 (-100.0144, 58.9621) -> (-99.0144, 58.9451)
  line L63 (-100.0144, 66.9914) -> (-100.0144, 58.9621)
  line L64 (-100.9644, 67.9414) -> (-100.0144, 66.9914)
  line L65 (-99.9644, -52.9879) -> (-99.9644, -60.9879)
  line L66 (-98.9644, -52.9879) -> (-99.9644, -52.9879)
  line L67 (-98.9644, 58.9942) -> (-98.9644, -52.9879)
  line L68 (-99.9644, 59.0113) -> (-98.9644, 58.9942)
  line L69 (-99.9644, 67.0121) -> (-99.9644, 59.0113)
  line L70 (-100.9644, -61.9879) -> (-99.9644, -60.9879)
  line L71 (-100.9644, 68.0121) -> (-99.9644, 67.0121)
  circle C1 centre (-24.4644, 61.5121) radius 1.7
  circle C2 centre (-93.9644, 54.5121) radius 1.7
  circle C3 centre (-87.4644, -55.4879) radius 1.7
  circle C4 centre (-17.4644, -48.4879) radius 1.7
  circle C5 centre (-24.4644, -55.4879) radius 1.7
  circle C6 centre (-93.9644, -48.4879) radius 1.7
  circle C7 centre (-87.4644, 61.5121) radius 1.7
  circle C8 centre (-17.4644, 54.5121) radius 1.7
  point P69 (-100.9644, 68.0121)
  point P74 (-100.9644, 68.0121)
  point P68 (-100.9644, -61.9879)
  point P75 (-100.9644, -61.9879)
  point P82 (-100.9644, 67.9414)
  point P83 (-100.9644, -61.9172)
  point P90 (-100.9644, -61.9879)
  point P91 (-100.9644, 68.0121)
  point P77 (-100.0144, -52.9379)
  point P80 (-100.0144, 58.9621)
  coincident P69 P74
  coincident P68 P75
  coincident L47 P82
  coincident L51 P83
  coincident P68 P90
  parallel L58 L70
  coincident P69 P91
  dimension "d147_3_1" distance L57 L63 = 0.95 (= "side_wall_thick1")
  dimension "d148_3_1" distance L57 L61 = 1.95 (= "side_wall_thick2")
  dimension "d151_3_1" distance L57 L59 = 0.95 (= "side_wall_thick1")
  dimension "d157_3_1" distance L64 L71 = 0.05 (= "wall_clearance")
  dimension "d158_3_1" distance L58 L70 = 0.05 (= "wall_clearance")
  dimension "wall_rorner_angle_3_1" angle L46 L71 = 45
  dimension "d165_3_1" angle L52 L70 = 45 (= "wall_rorner_angle_3_1")
  dimension "d170_3_1" distance P75 P77 = 9.05
  dimension "d175_3_1" distance P74 P80 = 9.05 (= "side_wall_col_length")
extrude "Extrude1" new body sketch "wall_base" profile of L47 L48 L50 L51 L57 L58 L59 L62 L61 L60 L63 L64 blind 69.9 (= "column_height - ( 2 * wall_clearance )") named "d128_3_1" from offset 0.05 (= "wall_clearance") named "d127_3_1" bodies "side cover"
sketch "Sketch3" plane through (100.9644, 0, 0) normal (1, 0, 0) x axis (0, 1, 0)
  line L1 (61.9172, 5.05) -> (-67.9414, 5.05)
  line L2 (61.9172, 74.95) -> (61.9172, 5.05)
  line L3 (-67.9414, 74.95) -> (61.9172, 74.95)
  line L4 (-67.9414, 5.05) -> (-67.9414, 74.95)
  line L5 (61.9172, 74.95) -> (-67.9414, 74.95)
  line L6 (61.9172, 74.95) -> (61.9172, 5.05)
  line L7 (61.9172, 5.05) -> (-67.9414, 5.05)
  line L8 (-67.9414, 74.95) -> (-67.9414, 5.05)
  line L9 (-57.9414, 64.95) -> (51.9172, 64.95)
  line L10 (-57.9414, 15.05) -> (-57.9414, 64.95)
  line L11 (51.9172, 15.05) -> (-57.9414, 15.05)
  line L12 (51.9172, 64.95) -> (51.9172, 15.05)
  circle C1 centre (-62.995, 60) radius 1.7
  circle C2 centre (-62.995, 20) radius 1.7
  circle C3 centre (56.9879, 60) radius 1.7
  circle C4 centre (56.9879, 20) radius 1.7
hole "Hole1" HoleDepth 4 named "d134_2_1" HoleDiameter 3.4 named "d135_2_1" TipAngle 118 named "d136_2_1"
sketch "Side locks" plane through (100.9644, 0, 0) normal (1, 0, 0) x axis (0, 1, 0)
  line L1 (61.9172, 74.95) -> (61.9172, 5.05)
  line L2 (-67.9414, 74.95) -> (61.9172, 74.95)
  line L3 (-67.9414, 5.05) -> (-67.9414, 74.95)
  line L4 (61.9172, 5.05) -> (-67.9414, 5.05)
  line L5 (-3.0121, 22.271) -> (-3.0121, 127.629)
  line L6 (25.9775, 40) -> (-161.8603, 40)
  line L7 (-67.9414, 64.95) -> (-67.9414, 74.95)
  line L8 (-61.9414, 74.95) -> (-67.9414, 74.95)
  line L9 (-61.9414, 59.95) -> (-61.9414, 74.95)
  line L10 (-67.9414, 64.95) -> (-61.9414, 59.95)
  line L11 (-67.9471, 64.9636) -> (-73.8914, 60.0101)
  line L12 (-73.8914, 60.0101) -> (-73.8914, 74.9101)
  line L13 (-67.9414, 64.9636) -> (-67.9471, 64.9636)
  line L14 (-67.9414, 74.9101) -> (-73.8914, 74.9101)
  line L15 (-67.9414, 5.0899) -> (-73.8914, 5.0899)
  line L16 (-73.8914, 19.9899) -> (-73.8914, 5.0899)
  line L17 (-67.9471, 15.0364) -> (-73.8914, 19.9899)
  line L18 (-67.9414, 15.0364) -> (-67.9471, 15.0364)
  line L19 (-67.9414, 15.05) -> (-67.9414, 5.05)
  line L20 (-61.9414, 5.05) -> (-67.9414, 5.05)
  line L21 (-61.9414, 20.05) -> (-61.9414, 5.05)
  line L22 (-67.9414, 15.05) -> (-61.9414, 20.05)
  line L23 (61.9172, 64.95) -> (61.9172, 74.95)
  line L24 (55.9172, 74.95) -> (61.9172, 74.95)
  line L25 (55.9172, 59.95) -> (55.9172, 74.95)
  line L26 (61.9172, 64.95) -> (55.9172, 59.95)
  line L27 (61.9172, 74.9101) -> (67.8672, 74.9101)
  line L28 (67.8672, 60.0101) -> (67.8672, 74.9101)
  line L29 (61.9172, 64.9636) -> (61.9229, 64.9636)
  line L30 (61.9229, 64.9636) -> (67.8672, 60.0101)
  line L31 (61.9172, 5.0899) -> (67.8672, 5.0899)
  line L32 (67.8672, 19.9899) -> (67.8672, 5.0899)
  line L33 (61.9172, 15.0364) -> (61.9229, 15.0364)
  line L34 (61.9229, 15.0364) -> (67.8672, 19.9899)
  line L35 (61.9172, 15.05) -> (61.9172, 5.05)
  line L36 (55.9172, 5.05) -> (61.9172, 5.05)
  line L37 (55.9172, 20.05) -> (55.9172, 5.05)
  line L38 (61.9172, 15.05) -> (55.9172, 20.05)
  point P17 (-67.9414, 64.9636)
  point P18 (-67.9414, 74.9101)
  point P10 (-67.9414, 74.95)
  point P24 (-67.9414, 5.05)
  point P11 (-67.9414, 64.95)
  point P25 (-67.9414, 15.05)
  point P12 (-61.9414, 74.95)
  point P26 (-61.9414, 5.05)
  point P13 (-61.9414, 59.95)
  point P27 (-61.9414, 20.05)
  point P14 (-67.9471, 64.9636)
  point P22 (-67.9471, 15.0364)
  point P15 (-73.8914, 60.0101)
  point P21 (-73.8914, 19.9899)
  point P16 (-73.8914, 74.9101)
  point P19 (-73.8914, 5.0899)
  point P23 (-67.9414, 15.0364)
  point P20 (-67.9414, 5.0899)
  point P28 (61.9172, 74.95)
  point P29 (61.9172, 64.95)
  point P30 (55.9172, 74.95)
  point P31 (55.9172, 59.95)
  point P35 (61.9229, 64.9636)
  point P34 (67.8672, 60.0101)
  point P32 (67.8672, 74.9101)
  point P36 (61.9172, 64.9636)
  point P33 (61.9172, 74.9101)
  point P37 (67.8672, 5.0899)
  point P38 (61.9172, 5.0899)
  point P39 (67.8672, 19.9899)
  point P40 (61.9229, 15.0364)
  point P41 (61.9172, 15.0364)
  point P42 (61.9172, 5.05)
  point P43 (61.9172, 15.05)
  point P44 (55.9172, 5.05)
  point P45 (55.9172, 20.05)
  vertical L5
  perpendicular L1 L6
  coincident L7 P17
  horizontal L14
  coincident L3 P18
  symmetric L6 P10 P24
  symmetric L6 P11 P25
  symmetric L6 P12 P26
  symmetric L6 P13 P27
  symmetric L6 P14 P22
  symmetric L6 P15 P21
  symmetric L6 P16 P19
  symmetric L6 P17 P23
  symmetric L6 P18 P20
  midpoint L2 L5
  midpoint L3 L6
  symmetric L5 P10 P28
  symmetric L5 P11 P29
  symmetric L5 P12 P30
  symmetric L5 P13 P31
  symmetric L5 P14 P35
  symmetric L5 P15 P34
  symmetric L5 P16 P32
  symmetric L5 P17 P36
  symmetric L5 P18 P33
  symmetric L5 P19 P37
  symmetric L5 P20 P38
  symmetric L5 P21 P39
  symmetric L5 P22 P40
  symmetric L5 P23 P41
  symmetric L5 P24 P42
  symmetric L5 P25 P43
  symmetric L5 P26 P44
  symmetric L5 P27 P45
  dimension "d315_3_1" distance P12 P13 = 15 (= "join_width2")
  dimension "d316_3_1" distance P10 P11 = 10 (= "join_width1")
  dimension "d317_3_1" distance P10 P12 = 6 (= "join_depth * 2")
  dimension "d320_3_1" distance P16 P18 = 5.95 (= "join_depth * 2 - wall_clearance")
  dimension "d321_3_1" distance P15 P16 = 14.9 (= "join_width2 - 2 * wall_clearance")
position "Position25"
extrude "Extrude3" add sketch "Side locks" profile of L2 L3 L4 L7 L8 L9 L10 L12 L11 L13 L14 L15 L16 L17 L18 L19 L20 L21 L22 against normal blind 0.95 named "d326_1" (magnitude of "-side_wall_thick1")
